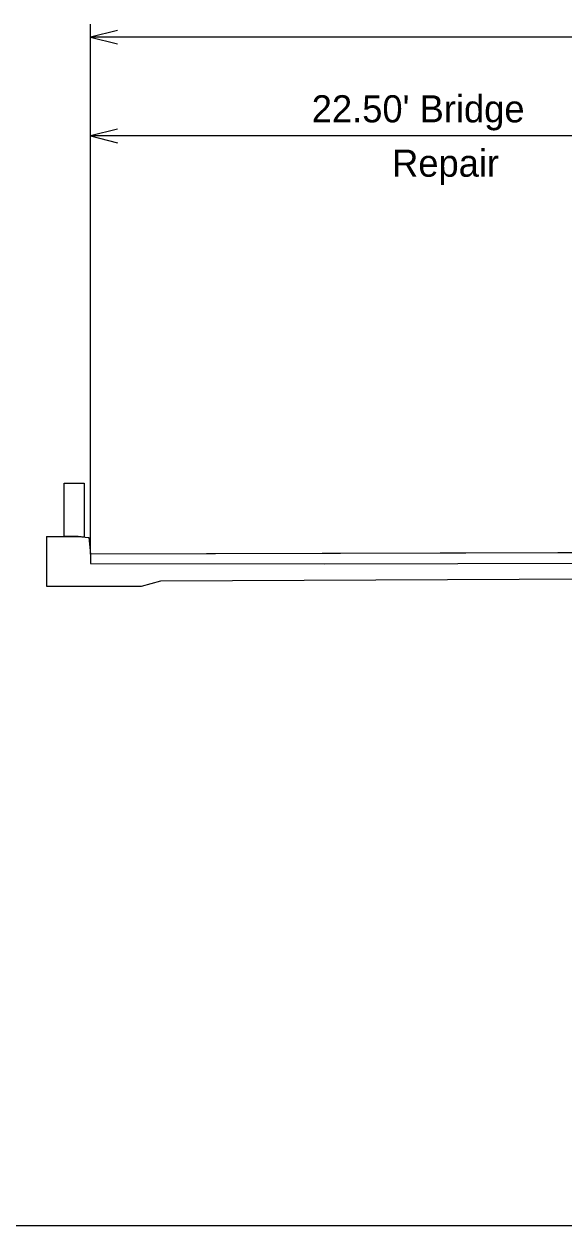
# Model space of a CAD drawing. Extents: x 8771 to 81668, y 6145 to 11018.
# Drawn here: x 14569 to 15021, y 7924 to 8930 of the extents above; entities that cross this region are included whole.
import ezdxf

# ---------------------------------------------------------------- set-up
doc = ezdxf.new("R2010")
doc.units = 0
for name, color, linetype in [('dsnCellElements', 7, 'Continuous'), ('DsnShtRevisedText', 7, 'Continuous'), ('SheetBorder', 7, 'Continuous'), ('ShtPlotIdentification', 7, 'Continuous')]:
    doc.layers.add(name, color=color, linetype=linetype)

msp = doc.modelspace()

# ---------------------------------------------------------------- linework, layer by layer
at = {"layer": 'dsnCellElements'}
for p, q in [((14624.8, 8486.3), (14624.8, 8929.9)), ((15873.4, 8919), (14624.8, 8919)), ((15249.1, 8836.3), (14624.8, 8836.3)), ((14614.4, 8501.1), (14602.9, 8501.1)), ((14619.6, 8500.6), (14614.4, 8501.1)), ((14667.4, 8459.5), (14683.6, 8463.9)), ((14683.6, 8463.9), (15249.1, 8466.8))]:
    msp.add_line(p, q, dxfattribs=at)
for points in [[(14647.5, 8924.7), (14624.8, 8919), (14647.5, 8913.3)], [(14647.5, 8842), (14624.8, 8836.3), (14647.5, 8830.6)], [(14602.9, 8501.1), (14602.9, 8545.6), (14619.6, 8545.6), (14619.6, 8500.6)], [(14587.9, 8501.1), (14587.9, 8459.5), (14667.4, 8459.5)], [(14587.9, 8501.1), (14614.4, 8501.1), (14623.4, 8500.2), (14624.8, 8486.3)]]:
    msp.add_lwpolyline(points, dxfattribs=at)
at = {"layer": 'DsnShtRevisedText'}
msp.add_lwpolyline([(14602.9, 8501.1), (14602.9, 8545.6), (14619.6, 8545.6), (14619.6, 8500.6)], dxfattribs=at)
at = {"layer": 'SheetBorder'}
msp.add_lwpolyline([(13732.5, 9944), (16867.5, 9944), (16867.5, 7924), (13732.5, 7924)], close=True, dxfattribs=at)
at = {"layer": 'ShtPlotIdentification'}
for p, q in [((15249.1, 8487.9), (14624.8, 8486.3)), ((14820.8, 8478.2), (15249.1, 8479.5))]:
    msp.add_line(p, q, dxfattribs=at)
for points in [[(14818.6, 8486.8), (14624.8, 8486.3), (14624.8, 8478.6), (14820.8, 8478.2)], [(15249.1, 8484.1), (15249.1, 8487.9), (15239.9, 8487.9), (15221.4, 8487.8), (15195.4, 8487.8), (15162.7, 8487.7), (15115.5, 8487.6), (15050.3, 8487.4), (15015.8, 8487.3), (14818.6, 8486.8)]]:
    msp.add_lwpolyline(points, dxfattribs=at)

# ---------------------------------------------------------------- texts
at = {"layer": 'dsnCellElements'}
for s, height, p in [("22.50' Bridge", 22.709, (14809.9, 8847.7)), ('Repair', 22.71, (14877.1, 8802.2))]:
    msp.add_text(s, height=height, dxfattribs=at).set_placement(p)

doc.saveas('drawing.dxf')
